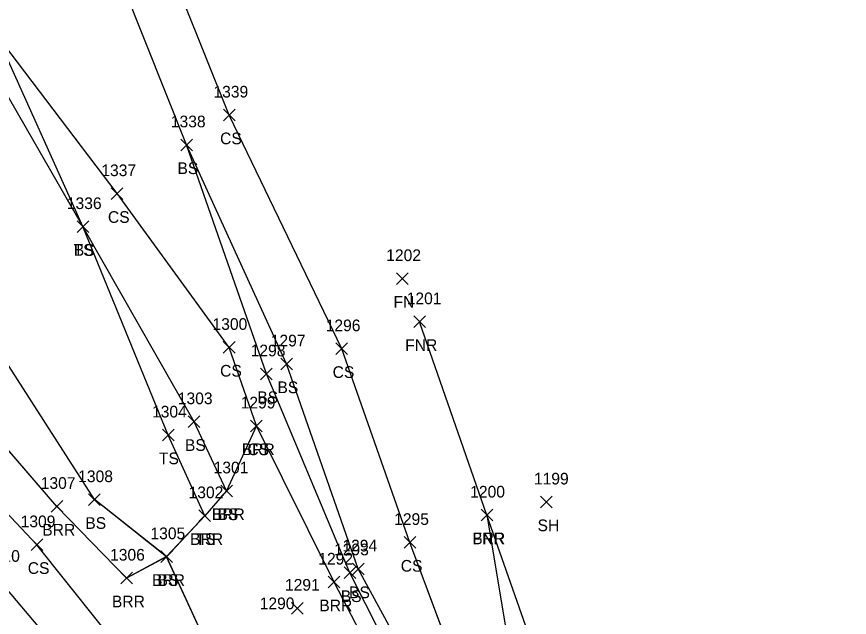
# Model space of a CAD drawing. Extents: x 1415642 to 1422021, y 544543 to 547232.
# Drawn here: x 1416364 to 1416506.5, y 546632.9 to 546735.7 of the extents above; entities that cross this region are included whole.
import ezdxf

# ---------------------------------------------------------------- set-up
doc = ezdxf.new("R2010")
doc.units = 0
for name, color, linetype in [('L_A', 7, 'Continuous'), ('L_I', 7, 'Continuous'), ('L_TIC', 7, 'Continuous'), ('LABL', 7, 'Continuous'), ('LELB', 7, 'Continuous'), ('LFNC', 7, 'Continuous')]:
    doc.layers.add(name, color=color, linetype=linetype)

msp = doc.modelspace()

# ---------------------------------------------------------------- linework, layer by layer
at = {"layer": 'L_TIC'}
for points in [[(1416399.37, 546717.89), (1416401.37, 546719.89)], [(1416401.37, 546717.89), (1416399.37, 546719.89)], [(1416392.07, 546712.79), (1416394.07, 546714.79)], [(1416394.07, 546712.79), (1416392.07, 546714.79)], [(1416392.07, 546712.79), (1416394.07, 546714.79)], [(1416394.07, 546712.79), (1416392.07, 546714.79)], [(1416380.17, 546704.43), (1416382.17, 546706.43)], [(1416382.17, 546704.43), (1416380.17, 546706.43)], [(1416374.33, 546698.79), (1416376.33, 546700.79)], [(1416376.33, 546698.79), (1416374.33, 546700.79)], [(1416374.33, 546698.79), (1416376.33, 546700.79)], [(1416376.33, 546698.79), (1416374.33, 546700.79)], [(1416429.01, 546689.89), (1416431.01, 546691.89)], [(1416431.01, 546689.89), (1416429.01, 546691.89)], [(1416431.95, 546682.5), (1416433.95, 546684.5)], [(1416433.95, 546682.5), (1416431.95, 546684.5)], [(1416399.36, 546678.1), (1416401.36, 546680.1)], [(1416401.36, 546678.1), (1416399.36, 546680.1)], [(1416418.63, 546677.87), (1416420.63, 546679.87)], [(1416420.63, 546677.87), (1416418.63, 546679.87)], [(1416409.18, 546675.27), (1416411.18, 546677.27)], [(1416411.18, 546675.27), (1416409.18, 546677.27)], [(1416405.73, 546673.57), (1416407.73, 546675.57)], [(1416407.73, 546673.57), (1416405.73, 546675.57)], [(1416393.35, 546665.38), (1416395.35, 546667.38)], [(1416395.35, 546665.38), (1416393.35, 546667.38)], [(1416404.03, 546664.65), (1416406.03, 546666.65)], [(1416406.03, 546664.65), (1416404.03, 546666.65)], [(1416404.03, 546664.65), (1416406.03, 546666.65)], [(1416406.03, 546664.65), (1416404.03, 546666.65)], [(1416388.93, 546663.1), (1416390.93, 546665.1)], [(1416390.93, 546663.1), (1416388.93, 546665.1)], [(1416398.91, 546653.53), (1416400.91, 546655.53)], [(1416400.91, 546653.53), (1416398.91, 546655.53)], [(1416398.91, 546653.53), (1416400.91, 546655.53)], [(1416400.91, 546653.53), (1416398.91, 546655.53)], [(1416376.3, 546652.03), (1416378.3, 546654.03)], [(1416378.3, 546652.03), (1416376.3, 546654.03)], [(1416453.66, 546651.63), (1416455.66, 546653.63)], [(1416455.66, 546651.63), (1416453.66, 546653.63)], [(1416369.88, 546650.88), (1416371.88, 546652.88)], [(1416371.88, 546650.88), (1416369.88, 546652.88)], [(1416395.19, 546649.28), (1416397.19, 546651.28)], [(1416397.19, 546649.28), (1416395.19, 546651.28)], [(1416395.19, 546649.28), (1416397.19, 546651.28)], [(1416397.19, 546649.28), (1416395.19, 546651.28)], [(1416443.47, 546649.39), (1416445.47, 546651.39)], [(1416445.47, 546649.39), (1416443.47, 546651.39)], [(1416443.47, 546649.39), (1416445.47, 546651.39)], [(1416445.47, 546649.39), (1416443.47, 546651.39)], [(1416430.29, 546644.7), (1416432.29, 546646.7)], [(1416432.29, 546644.7), (1416430.29, 546646.7)], [(1416366.45, 546644.31), (1416368.45, 546646.31)], [(1416368.45, 546644.31), (1416366.45, 546646.31)], [(1416388.66, 546642.26), (1416390.66, 546644.26)], [(1416390.66, 546642.26), (1416388.66, 546644.26)], [(1416388.66, 546642.26), (1416390.66, 546644.26)], [(1416390.66, 546642.26), (1416388.66, 546644.26)], [(1416421.44, 546640.16), (1416423.44, 546642.16)], [(1416423.44, 546640.16), (1416421.44, 546642.16)], [(1416420.02, 546639.5), (1416422.02, 546641.5)], [(1416422.02, 546639.5), (1416420.02, 546641.5)], [(1416381.8, 546638.59), (1416383.8, 546640.59)], [(1416383.8, 546638.59), (1416381.8, 546640.59)], [(1416417.31, 546637.92), (1416419.31, 546639.92)], [(1416419.31, 546637.92), (1416417.31, 546639.92)], [(1416411.04, 546633.44), (1416413.04, 546635.44)], [(1416413.04, 546633.44), (1416411.04, 546635.44)]]:
    msp.add_lwpolyline(points, dxfattribs=at)
at = {"layer": 'LABL'}
for points in [[(1416444.47, 546650.39), (1416449.12, 546622.32), (1416453.47, 546601.16), (1416449.42, 546597.09), (1416447.84, 546594.51), (1416444.98, 546593.05), (1416441.96, 546593.48), (1416418.31, 546638.92), (1416405.03, 546665.65), (1416399.91, 546654.53), (1416396.19, 546650.28), (1416389.66, 546643.26), (1416382.8, 546639.59), (1416370.88, 546651.88), (1416331.53, 546697.52), (1416315.15, 546719.28), (1416313.42, 546715.93), (1416308.55, 546724.26), (1416301.62, 546736.74), (1416278.11, 546774.25)], [(1416444.47, 546650.39), (1416449.12, 546622.32), (1416453.47, 546601.16), (1416449.42, 546597.08), (1416447.84, 546594.51), (1416444.98, 546593.04), (1416441.96, 546593.48), (1416418.31, 546638.92), (1416405.03, 546665.65), (1416399.91, 546654.53), (1416396.19, 546650.28), (1416389.66, 546643.27), (1416382.81, 546639.59), (1416370.88, 546651.88), (1416331.54, 546697.52), (1416315.15, 546719.28), (1416313.42, 546715.93), (1416308.55, 546724.26), (1416301.62, 546736.74), (1416278.12, 546774.25)]]:
    msp.add_lwpolyline(points, dxfattribs=at)
at = {"layer": 'LELB'}
for points in [[(1416396.19, 546650.28), (1416389.93, 546664.1), (1416375.33, 546699.79), (1416360.48, 546732.7), (1416344.12, 546775.76), (1416313.07, 546810.87), (1416283.75, 546829.86), (1416246.42, 546852.16), (1416221.38, 546861.32), (1416210.74, 546868.88), (1416211.4, 546870.4), (1416221.96, 546889.07)], [(1416396.19, 546650.28), (1416389.93, 546664.1), (1416375.33, 546699.79), (1416360.49, 546732.7), (1416344.12, 546775.76), (1416313.07, 546810.87), (1416283.75, 546829.86), (1416246.42, 546852.16), (1416221.38, 546861.32), (1416210.75, 546868.87), (1416211.4, 546870.4), (1416221.97, 546889.07)], [(1416399.91, 546654.53), (1416394.35, 546666.38), (1416375.33, 546699.79), (1416357.07, 546731.49), (1416339.46, 546773.58), (1416310.34, 546806.72), (1416282.7, 546825.53), (1416242.81, 546844.04), (1416212.63, 546849.89), (1416203.83, 546852.66), (1416197.94, 546856.2), (1416209.64, 546861.99)], [(1416399.91, 546654.53), (1416394.35, 546666.37), (1416375.33, 546699.79), (1416357.08, 546731.49), (1416339.45, 546773.58), (1416310.34, 546806.72), (1416282.71, 546825.53), (1416242.81, 546844.04), (1416212.62, 546849.89), (1416203.83, 546852.66), (1416197.94, 546856.21), (1416209.64, 546861.99)], [(1416487.57, 546505.93), (1416480.71, 546505.12), (1416469.86, 546502.72), (1416462.76, 546510.55), (1416442.83, 546541.19), (1416430.44, 546560.72), (1416424.35, 546585.18), (1416398.34, 546624.28), (1416389.66, 546643.26), (1416377.3, 546653.03), (1416344.54, 546704.05), (1416343.42, 546724.77), (1416329.35, 546768.04), (1416303.68, 546799.52), (1416274.8, 546819.39), (1416239.26, 546839.41), (1416210.61, 546845.46), (1416203.47, 546849.21), (1416195, 546854.49)], [(1416487.57, 546505.93), (1416480.71, 546505.12), (1416469.86, 546502.72), (1416462.76, 546510.55), (1416442.83, 546541.19), (1416430.44, 546560.72), (1416424.35, 546585.18), (1416398.34, 546624.28), (1416389.66, 546643.27), (1416377.3, 546653.03), (1416344.54, 546704.05), (1416343.42, 546724.76), (1416329.35, 546768.04), (1416303.68, 546799.52), (1416274.8, 546819.4), (1416239.26, 546839.41), (1416210.61, 546845.46), (1416203.48, 546849.21), (1416195, 546854.49)], [(1416488.29, 546504.83), (1416488.12, 546506.46), (1416480.5, 546522.11), (1416462.74, 546551.59), (1416447.84, 546594.51), (1416422.44, 546641.16), (1416410.18, 546676.27), (1416393.07, 546713.79), (1416378.8, 546749.63), (1416367.97, 546783.97), (1416347.35, 546811.63), (1416340.26, 546839.45), (1416338.76, 546849.28)], [(1416488.29, 546504.83), (1416488.12, 546506.46), (1416480.5, 546522.11), (1416462.74, 546551.59), (1416447.84, 546594.51), (1416422.44, 546641.16), (1416410.17, 546676.27), (1416393.07, 546713.79), (1416378.8, 546749.63), (1416367.97, 546783.97), (1416347.34, 546811.63), (1416340.26, 546839.45), (1416338.76, 546849.28)], [(1416449.42, 546597.09), (1416431.29, 546645.7), (1416419.63, 546678.87), (1416400.37, 546718.89), (1416388.41, 546748.65), (1416375.25, 546786.59), (1416353.32, 546816.02), (1416347.15, 546837.59)], [(1416449.42, 546597.08), (1416431.29, 546645.7), (1416419.63, 546678.87), (1416400.37, 546718.89), (1416388.42, 546748.65), (1416375.25, 546786.59), (1416353.33, 546816.03), (1416347.15, 546837.59)], [(1416462.64, 546496.11), (1416437.87, 546538.89), (1416411.19, 546576.82), (1416382.17, 546614.17), (1416360.8, 546639.39), (1416323.65, 546683.15), (1416301.53, 546707.03), (1416273.6, 546735.69), (1416258.67, 546751.22), (1416224.41, 546784.74), (1416201.13, 546806.07), (1416169.09, 546832.26)], [(1416462.64, 546496.11), (1416437.87, 546538.89), (1416411.18, 546576.82), (1416382.17, 546614.17), (1416360.8, 546639.39), (1416323.65, 546683.15), (1416301.53, 546707.03), (1416273.6, 546735.69), (1416258.67, 546751.22), (1416224.4, 546784.74), (1416201.13, 546806.07), (1416169.09, 546832.26)], [(1416405.03, 546665.65), (1416400.36, 546679.1), (1416381.17, 546705.43), (1416360.48, 546732.7)], [(1416405.03, 546665.65), (1416400.36, 546679.1), (1416381.17, 546705.43), (1416360.49, 546732.7)], [(1416488.29, 546504.83), (1416487.21, 546504.52), (1416487.57, 546505.93), (1416477.24, 546519.91), (1416458.18, 546549.98), (1416444.98, 546593.05), (1416421.02, 546640.5), (1416406.73, 546674.57), (1416393.07, 546713.79)], [(1416488.29, 546504.83), (1416487.21, 546504.52), (1416487.57, 546505.93), (1416477.24, 546519.91), (1416458.18, 546549.99), (1416444.98, 546593.04), (1416421.01, 546640.5), (1416406.73, 546674.57), (1416393.07, 546713.79)], [(1416430.44, 546560.72), (1416417.31, 546581.34), (1416388.22, 546619.27), (1416367.45, 546645.31), (1416327.63, 546687.63), (1416307.15, 546711.36)], [(1416430.44, 546560.72), (1416417.31, 546581.35), (1416388.22, 546619.27), (1416367.44, 546645.31), (1416327.63, 546687.64), (1416307.15, 546711.36)]]:
    msp.add_lwpolyline(points, dxfattribs=at)
at = {"layer": 'LFNC'}
for points in [[(1416506.5, 546506.54), (1416496.1, 546503.23), (1416493.36, 546510.33), (1416488.7, 546524.12), (1416477.63, 546555.25), (1416468.51, 546581.39), (1416458.21, 546611.19), (1416444.47, 546650.39), (1416432.95, 546683.5)], [(1416506.5, 546506.54), (1416496.1, 546503.23), (1416493.36, 546510.33), (1416488.7, 546524.12), (1416477.63, 546555.24), (1416468.51, 546581.39), (1416458.21, 546611.19), (1416444.47, 546650.39), (1416432.95, 546683.5)]]:
    msp.add_lwpolyline(points, dxfattribs=at)

# ---------------------------------------------------------------- texts
at = {"layer": 'L_A'}
for s, p in [('CS', (1416398.81, 546713.89)), ('BS', (1416391.51, 546708.79)), ('BS', (1416391.51, 546708.79)), ('CS', (1416379.61, 546700.43)), ('TS', (1416373.74, 546694.79)), ('BS', (1416373.77, 546694.79)), ('FN', (1416428.49, 546685.89)), ('FNR', (1416430.49, 546678.5)), ('CS', (1416398.81, 546674.1)), ('CS', (1416418.07, 546673.87)), ('BS', (1416408.62, 546671.27)), ('BS', (1416405.17, 546669.57)), ('BS', (1416392.79, 546661.38)), ('BRR', (1416402.52, 546660.65)), ('CS', (1416403.47, 546660.65)), ('TS', (1416388.34, 546659.1)), ('BRR', (1416397.39, 546649.53)), ('BS', (1416398.35, 546649.53)), ('BS', (1416375.74, 546648.03)), ('SH', (1416453.14, 546647.63)), ('BRR', (1416368.37, 546646.88)), ('BRR', (1416393.67, 546645.28)), ('TS', (1416394.59, 546645.28)), ('BRR', (1416441.96, 546645.39)), ('FNR', (1416442.01, 546645.39)), ('CS', (1416365.89, 546640.31)), ('CS', (1416429.73, 546640.7)), ('BRR', (1416387.15, 546638.26)), ('BS', (1416388.1, 546638.26)), ('BS', (1416420.88, 546636.16)), ('BRR', (1416380.29, 546634.59)), ('BS', (1416419.46, 546635.5)), ('BRR', (1416415.79, 546633.92))]:
    msp.add_text(s, height=2, dxfattribs=at).set_placement(p)
at = {"layer": 'L_I'}
for s, p in [('1339', (1416397.67, 546721.89)), ('1338', (1416390.38, 546716.79)), ('1338', (1416390.38, 546716.79)), ('1337', (1416378.48, 546708.43)), ('1336', (1416372.58, 546702.79)), ('1336', (1416372.58, 546702.79)), ('1202', (1416427.24, 546693.89)), ('1201', (1416430.75, 546686.5)), ('1300', (1416397.51, 546682.1)), ('1296', (1416416.88, 546681.87)), ('1297', (1416407.48, 546679.27)), ('1298', (1416404.04, 546677.57)), ('1303', (1416391.57, 546669.38)), ('1299', (1416402.33, 546668.65)), ('1299', (1416402.33, 546668.65)), ('1304', (1416387.16, 546667.1)), ('1301', (1416397.7, 546657.53)), ('1301', (1416397.7, 546657.53)), ('1308', (1416374.52, 546656.03)), ('1307', (1416368.11, 546654.88)), ('1199', (1416452.52, 546655.63)), ('1302', (1416393.41, 546653.28)), ('1302', (1416393.41, 546653.28)), ('1200', (1416441.61, 546653.39)), ('1200', (1416441.61, 546653.39)), ('1295', (1416428.6, 546648.7)), ('1309', (1416364.67, 546648.31)), ('1305', (1416386.89, 546646.26)), ('1305', (1416386.89, 546646.26)), ('1293', (1416418.32, 546643.5)), ('1294', (1416419.74, 546644.16)), ('1310', (1416358.59, 546642.39)), ('1306', (1416379.98, 546642.59)), ('1292', (1416415.61, 546641.92)), ('1291', (1416409.91, 546637.44)), ('1290', (1416405.59, 546634.27))]:
    msp.add_text(s, height=2, dxfattribs=at).set_placement(p)

doc.saveas('drawing.dxf')
